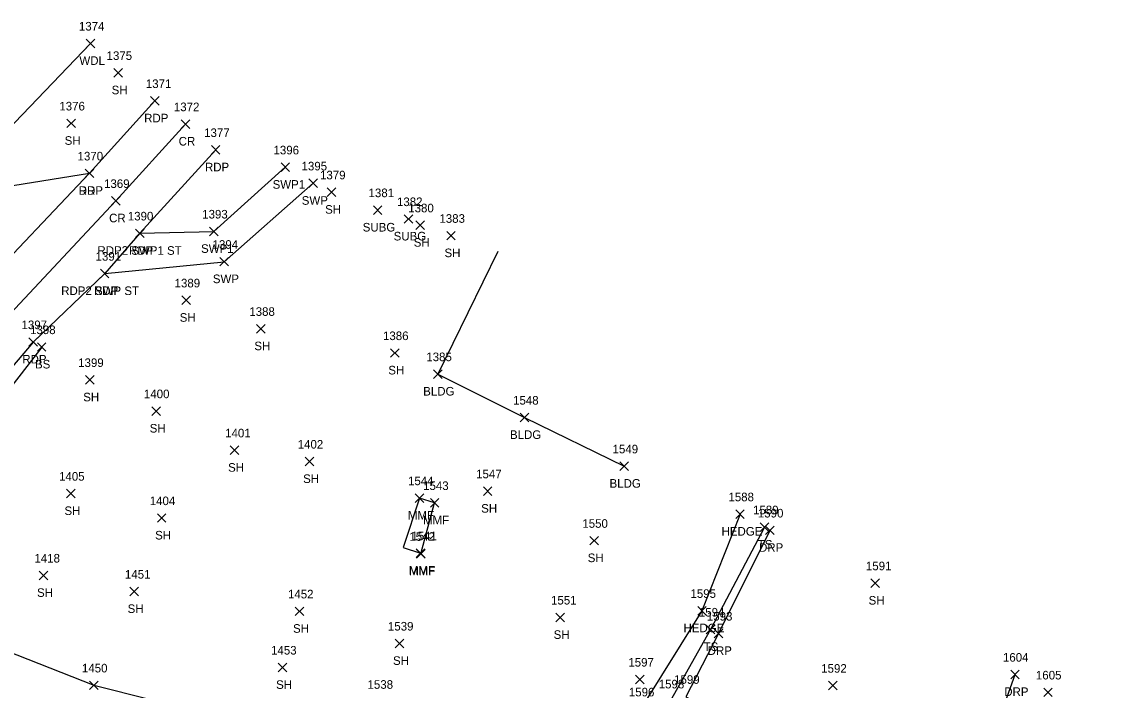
# Model space of a CAD drawing. Extents: x 1586965 to 1590952, y 716317 to 720029.
# Drawn here: x 1587807.3 to 1588061.4, y 719869.6 to 720025.2 of the extents above; entities that cross this region are included whole.
import ezdxf

# ---------------------------------------------------------------- set-up
doc = ezdxf.new("R2010")
doc.units = 0
for name, color, linetype in [('L_A', 7, 'Continuous'), ('L_I', 7, 'Continuous'), ('L_TIC', 7, 'Continuous'), ('LAHR', 7, 'Continuous'), ('LAWA', 7, 'Continuous'), ('LBC', 7, 'Continuous'), ('LDEFAULT', 7, 'Continuous'), ('LELB', 7, 'Continuous'), ('P_A', 7, 'Continuous'), ('P_I', 7, 'Continuous'), ('P_TIC', 7, 'Continuous'), ('PET', 7, 'Continuous'), ('PRC', 7, 'Continuous'), ('R_A', 7, 'Continuous'), ('R_I', 7, 'Continuous'), ('R_TIC', 7, 'Continuous'), ('RDP', 7, 'Continuous'), ('RSW', 7, 'Continuous'), ('U_A', 7, 'Continuous'), ('U_I', 7, 'Continuous'), ('U_TIC', 7, 'Continuous')]:
    doc.layers.add(name, color=color, linetype=linetype)

msp = doc.modelspace()

# ---------------------------------------------------------------- linework, layer by layer
at = {"layer": 'L_TIC'}
for points in [[(1587822.3, 720019.21), (1587824.3, 720021.21)], [(1587824.3, 720019.21), (1587822.3, 720021.21)], [(1587828.74, 720012.36), (1587830.74, 720014.36)], [(1587830.74, 720012.36), (1587828.74, 720014.36)], [(1587817.79, 720000.6), (1587819.79, 720002.6)], [(1587819.79, 720000.6), (1587817.79, 720002.6)], [(1587878.49, 719984.56), (1587880.49, 719986.56)], [(1587880.49, 719984.56), (1587878.49, 719986.56)], [(1587899.13, 719976.88), (1587901.13, 719978.88)], [(1587901.13, 719976.88), (1587899.13, 719978.88)], [(1587906.31, 719974.44), (1587908.31, 719976.44)], [(1587908.31, 719974.44), (1587906.31, 719976.44)], [(1587844.6, 719959.4), (1587846.6, 719961.4)], [(1587846.6, 719959.4), (1587844.6, 719961.4)], [(1587862, 719952.77), (1587864, 719954.77)], [(1587864, 719952.77), (1587862, 719954.77)], [(1587810.93, 719948.52), (1587812.93, 719950.52)], [(1587812.93, 719948.52), (1587810.93, 719950.52)], [(1587893.21, 719947.13), (1587895.21, 719949.13)], [(1587895.21, 719947.13), (1587893.21, 719949.13)], [(1587903.24, 719942.22), (1587905.24, 719944.22)], [(1587905.24, 719942.22), (1587903.24, 719944.22)], [(1587822.13, 719940.87), (1587824.13, 719942.87)], [(1587824.13, 719940.87), (1587822.13, 719942.87)], [(1587837.61, 719933.6), (1587839.61, 719935.6)], [(1587839.61, 719933.6), (1587837.61, 719935.6)], [(1587923.46, 719932.11), (1587925.46, 719934.11)], [(1587925.46, 719932.11), (1587923.46, 719934.11)], [(1587855.88, 719924.48), (1587857.88, 719926.48)], [(1587857.88, 719924.48), (1587855.88, 719926.48)], [(1587873.36, 719921.86), (1587875.36, 719923.86)], [(1587875.36, 719921.86), (1587873.36, 719923.86)], [(1587946.66, 719920.76), (1587948.66, 719922.76)], [(1587948.66, 719920.76), (1587946.66, 719922.76)], [(1587817.75, 719914.4), (1587819.75, 719916.4)], [(1587819.75, 719914.4), (1587817.75, 719916.4)], [(1587898.98, 719913.35), (1587900.98, 719915.35)], [(1587900.98, 719913.35), (1587898.98, 719915.35)], [(1587914.85, 719914.95), (1587916.85, 719916.95)], [(1587916.85, 719914.95), (1587914.85, 719916.95)], [(1587902.5, 719912.22), (1587904.5, 719914.22)], [(1587904.5, 719912.22), (1587902.5, 719914.22)], [(1587838.88, 719908.7), (1587840.88, 719910.7)], [(1587840.88, 719908.7), (1587838.88, 719910.7)], [(1587973.65, 719909.6), (1587975.65, 719911.6)], [(1587975.65, 719909.6), (1587973.65, 719911.6)], [(1587979.38, 719906.57), (1587981.38, 719908.57)], [(1587981.38, 719906.57), (1587979.38, 719908.57)], [(1587939.69, 719903.43), (1587941.69, 719905.43)], [(1587941.69, 719903.43), (1587939.69, 719905.43)], [(1587899.2, 719900.54), (1587901.2, 719902.54)], [(1587901.2, 719900.54), (1587899.2, 719902.54)], [(1587899.29, 719900.39), (1587901.29, 719902.39)], [(1587901.29, 719900.39), (1587899.29, 719902.39)], [(1587811.36, 719895.34), (1587813.36, 719897.34)], [(1587813.36, 719895.34), (1587811.36, 719897.34)], [(1588005.12, 719893.54), (1588007.12, 719895.54)], [(1588007.12, 719893.54), (1588005.12, 719895.54)], [(1587832.46, 719891.59), (1587834.46, 719893.59)], [(1587834.46, 719891.59), (1587832.46, 719893.59)], [(1587871.01, 719886.98), (1587873.01, 719888.98)], [(1587873.01, 719886.98), (1587871.01, 719888.98)], [(1587931.73, 719885.56), (1587933.73, 719887.56)], [(1587933.73, 719885.56), (1587931.73, 719887.56)], [(1587964.79, 719887.11), (1587966.79, 719889.11)], [(1587966.79, 719887.11), (1587964.79, 719889.11)], [(1587966.76, 719882.76), (1587968.76, 719884.76)], [(1587968.76, 719882.76), (1587966.76, 719884.76)], [(1587894.31, 719879.5), (1587896.31, 719881.5)], [(1587896.31, 719879.5), (1587894.31, 719881.5)], [(1587867.07, 719873.91), (1587869.07, 719875.91)], [(1587869.07, 719873.91), (1587867.07, 719875.91)], [(1587823.09, 719869.75), (1587825.09, 719871.75)], [(1587825.09, 719869.75), (1587823.09, 719871.75)], [(1587995.27, 719869.68), (1587997.27, 719871.68)], [(1587997.27, 719869.68), (1587995.27, 719871.68)], [(1588045.42, 719868.11), (1588047.42, 719870.11)], [(1588047.42, 719868.11), (1588045.42, 719870.11)]]:
    msp.add_lwpolyline(points, dxfattribs=at)
at = {"layer": 'LAHR'}
msp.add_lwpolyline([(1587974.65, 719910.6), (1587965.79, 719888.11), (1587951.5, 719865.17)], dxfattribs=at)
at = {"layer": 'LAWA'}
msp.add_lwpolyline([(1587759.78, 720023.49), (1587775.56, 720010.22), (1587793.08, 719998.06), (1587803.89, 719999.91), (1587823.3, 720020.21)], dxfattribs=at)
at = {"layer": 'LBC'}
msp.add_lwpolyline([(1587918.19, 719971.72), (1587904.24, 719943.22), (1587924.46, 719933.11), (1587947.66, 719921.76)], dxfattribs=at)
at = {"layer": 'LDEFAULT'}
for points in [[(1587896.16, 719902.84), (1587900.2, 719901.54), (1587900.29, 719901.39), (1587903.5, 719913.22), (1587899.98, 719914.35)], [(1587899.98, 719914.35), (1587896.16, 719902.84)]]:
    msp.add_lwpolyline(points, dxfattribs=at)
at = {"layer": 'LELB'}
for points in [[(1587811.93, 719949.52), (1587792.29, 719924.28), (1587790.61, 719906.24), (1587796.42, 719891.05), (1587800.94, 719879.86), (1587824.09, 719870.75), (1587863.89, 719860.75), (1587885.59, 719851.77), (1587915.12, 719838.63), (1587948, 719820.59), (1587984.49, 719804.22), (1588019.19, 719787.78), (1588025.35, 719786.55), (1588029.77, 719787.48), (1588038.8, 719793.55), (1588050.21, 719818.02), (1588057.55, 719835.32), (1588061.37, 719857.52)], [(1587811.93, 719949.52), (1587792.29, 719924.28), (1587790.61, 719906.24), (1587796.42, 719891.05), (1587800.94, 719879.86), (1587824.09, 719870.75), (1587863.89, 719860.75), (1587885.59, 719851.77), (1587915.12, 719838.63), (1587948, 719820.59), (1587984.49, 719804.22), (1588019.19, 719787.78), (1588025.35, 719786.55), (1588029.77, 719787.48), (1588038.8, 719793.55), (1588050.21, 719818.02), (1588057.55, 719835.32), (1588061.37, 719857.52)], [(1587980.38, 719907.57), (1587967.76, 719883.76), (1587958.41, 719867.03), (1587982.59, 719852.2), (1588028.36, 719838.74)], [(1587980.38, 719907.57), (1587967.76, 719883.76), (1587958.41, 719867.03), (1587982.59, 719852.2), (1588028.36, 719838.74)]]:
    msp.add_lwpolyline(points, dxfattribs=at)
at = {"layer": 'P_TIC'}
for points in [[(1587837.32, 720005.82), (1587839.32, 720007.82)], [(1587839.32, 720005.82), (1587837.32, 720007.82)], [(1587844.42, 720000.43), (1587846.42, 720002.43)], [(1587846.42, 720000.43), (1587844.42, 720002.43)], [(1587851.48, 719994.42), (1587853.48, 719996.42)], [(1587853.48, 719994.42), (1587851.48, 719996.42)], [(1587822.07, 719988.96), (1587824.07, 719990.96)], [(1587824.07, 719988.96), (1587822.07, 719990.96)], [(1587828.2, 719982.55), (1587830.2, 719984.55)], [(1587830.2, 719982.55), (1587828.2, 719984.55)], [(1587833.78, 719974.99), (1587835.78, 719976.99)], [(1587835.78, 719974.99), (1587833.78, 719976.99)], [(1587825.61, 719965.62), (1587827.61, 719967.62)], [(1587827.61, 719965.62), (1587825.61, 719967.62)], [(1587808.93, 719949.68), (1587810.93, 719951.68)], [(1587810.93, 719949.68), (1587808.93, 719951.68)]]:
    msp.add_lwpolyline(points, dxfattribs=at)
at = {"layer": 'PET'}
for points in [[(1587685.91, 719854.02), (1587701.42, 719870.84), (1587715.13, 719880.1), (1587736.18, 719901.89), (1587760.55, 719926.61), (1587776.13, 719942.57), (1587797.01, 719962.52), (1587823.07, 719989.96), (1587838.32, 720006.82)], [(1587852.48, 719995.42), (1587834.78, 719975.99), (1587826.61, 719966.62), (1587809.93, 719950.68), (1587788.43, 719925.43), (1587782.06, 719906.26), (1587783.24, 719885.08), (1587795.98, 719858.74)]]:
    msp.add_lwpolyline(points, dxfattribs=at)
at = {"layer": 'PRC'}
msp.add_lwpolyline([(1587717.2, 719859.97), (1587724.35, 719876.95), (1587738.37, 719893.54), (1587760.76, 719912.63), (1587787.69, 719938.18), (1587803.53, 719956.11), (1587829.2, 719983.55), (1587845.42, 720001.43)], dxfattribs=at)
msp.add_lwpolyline([(1587717.2, 719859.97), (1587724.35, 719876.95), (1587738.37, 719893.54), (1587760.76, 719912.63), (1587787.69, 719938.18), (1587803.53, 719956.11), (1587829.2, 719983.55), (1587845.42, 720001.43)], dxfattribs=at)
at = {"layer": 'R_TIC'}
for points in [[(1587867.7, 719990.37), (1587869.7, 719992.37)], [(1587869.7, 719990.37), (1587867.7, 719992.37)], [(1587822.07, 719988.96), (1587824.07, 719990.96)], [(1587824.07, 719988.96), (1587822.07, 719990.96)], [(1587874.17, 719986.64), (1587876.17, 719988.64)], [(1587876.17, 719986.64), (1587874.17, 719988.64)], [(1587833.78, 719974.99), (1587835.78, 719976.99)], [(1587835.78, 719974.99), (1587833.78, 719976.99)], [(1587851.03, 719975.44), (1587853.03, 719977.44)], [(1587853.03, 719975.44), (1587851.03, 719977.44)], [(1587853.44, 719968.39), (1587855.44, 719970.39)], [(1587855.44, 719968.39), (1587853.44, 719970.39)], [(1587825.61, 719965.62), (1587827.61, 719967.62)], [(1587827.61, 719965.62), (1587825.61, 719967.62)], [(1587980.59, 719905.83), (1587982.59, 719907.83)], [(1587982.59, 719905.83), (1587980.59, 719907.83)], [(1587968.62, 719881.82), (1587970.62, 719883.82)], [(1587970.62, 719881.82), (1587968.62, 719883.82)], [(1588037.73, 719872.26), (1588039.73, 719874.26)], [(1588039.73, 719872.26), (1588037.73, 719874.26)]]:
    msp.add_lwpolyline(points, dxfattribs=at)
at = {"layer": 'RDP'}
for points in [[(1587756.05, 720018.33), (1587771.73, 720004.93), (1587788.8, 719990.78), (1587803.23, 719986.78), (1587823.07, 719989.96)], [(1587981.59, 719906.83), (1587969.62, 719882.82), (1587961.99, 719868.1), (1587987.74, 719855.09), (1588029.05, 719846.17), (1588038.73, 719873.26)]]:
    msp.add_lwpolyline(points, dxfattribs=at)
at = {"layer": 'RSW'}
for points in [[(1587834.78, 719975.99), (1587852.03, 719976.44), (1587868.7, 719991.37)], [(1587826.61, 719966.62), (1587854.44, 719969.39), (1587875.17, 719987.64)]]:
    msp.add_lwpolyline(points, dxfattribs=at)
at = {"layer": 'U_TIC'}
for points in [[(1587889.21, 719980.41), (1587891.21, 719982.41)], [(1587891.21, 719980.41), (1587889.21, 719982.41)], [(1587896.42, 719978.33), (1587898.42, 719980.33)], [(1587898.42, 719978.33), (1587896.42, 719980.33)], [(1587950.32, 719871.11), (1587952.32, 719873.11)], [(1587952.32, 719871.11), (1587950.32, 719873.11)]]:
    msp.add_lwpolyline(points, dxfattribs=at)

# ---------------------------------------------------------------- texts
at = {"layer": 'L_A'}
for s, p in [('WDL', (1587820.72, 720015.21)), ('SH', (1587828.23, 720008.36)), ('SH', (1587817.28, 719996.6)), ('SH', (1587877.98, 719980.56)), ('SH', (1587898.62, 719972.88)), ('SH', (1587905.79, 719970.44)), ('SH', (1587844.09, 719955.4)), ('SH', (1587861.49, 719948.77)), ('BS', (1587810.37, 719944.52)), ('SH', (1587892.69, 719943.13)), ('SH', (1587821.61, 719936.87)), ('BLDG', (1587900.83, 719938.22)), ('SH', (1587837.1, 719929.6)), ('BLDG', (1587921.05, 719928.11)), ('SH', (1587855.37, 719920.48)), ('SH', (1587872.85, 719917.86)), ('BLDG', (1587944.25, 719916.76)), ('SH', (1587914.34, 719910.95)), ('SH', (1587817.24, 719910.4)), ('MMF', (1587897.26, 719909.35)), ('MMF', (1587900.78, 719908.22)), ('HEDGE', (1587970.35, 719905.6)), ('SH', (1587838.37, 719904.7)), ('TS', (1587978.79, 719902.57)), ('SH', (1587939.17, 719899.43)), ('MMF', (1587897.48, 719896.54)), ('MMF', (1587897.57, 719896.39)), ('SH', (1587810.85, 719891.34)), ('SH', (1588004.61, 719889.54)), ('SH', (1587831.95, 719887.59)), ('SH', (1587870.5, 719882.98)), ('HEDGE', (1587961.49, 719883.11)), ('SH', (1587931.22, 719881.56)), ('TS', (1587966.17, 719878.76)), ('SH', (1587893.8, 719875.5)), ('SH', (1587866.56, 719869.91))]:
    msp.add_text(s, height=2, dxfattribs=at).set_placement(p)
at = {"layer": 'L_I'}
for s, p in [('1374', (1587820.61, 720023.21)), ('1375', (1587827.05, 720016.36)), ('1376', (1587816.04, 720004.6)), ('1379', (1587876.79, 719988.56)), ('1380', (1587897.35, 719980.88)), ('1383', (1587904.61, 719978.44)), ('1389', (1587842.9, 719963.4)), ('1388', (1587860.31, 719956.77)), ('1398', (1587809.23, 719952.52)), ('1386', (1587891.46, 719951.13)), ('1385', (1587901.55, 719946.22)), ('1399', (1587820.43, 719944.87)), ('1400', (1587835.75, 719937.6)), ('1548', (1587921.77, 719936.11)), ('1401', (1587854.68, 719928.48)), ('1402', (1587871.59, 719925.86)), ('1549', (1587944.96, 719924.76)), ('1405', (1587815.98, 719918.4)), ('1547', (1587913.16, 719918.95)), ('1544', (1587897.29, 719917.35)), ('1543', (1587900.81, 719916.22)), ('1588', (1587971.95, 719913.6)), ('1404', (1587837.11, 719912.7)), ('1589', (1587977.68, 719910.57)), ('1550', (1587937.91, 719907.43)), ('1542', (1587897.6, 719904.39)), ('1541', (1587898.07, 719904.54)), ('1418', (1587810.24, 719899.34)), ('1451', (1587831.33, 719895.59)), ('1591', (1588003.99, 719897.54)), ('1452', (1587869.32, 719890.98)), ('1595', (1587963.1, 719891.11)), ('1551', (1587930.61, 719889.56)), ('1594', (1587965.07, 719886.76)), ('1539', (1587892.61, 719883.5)), ('1453', (1587865.38, 719877.91)), ('1450', (1587821.31, 719873.75)), ('1592', (1587993.57, 719873.68)), ('1538', (1587887.86, 719869.94)), ('1598', (1587955.71, 719870.03)), ('1605', (1588043.6, 719872.11)), ('1596', (1587948.75, 719868.17))]:
    msp.add_text(s, height=2, dxfattribs=at).set_placement(p)
at = {"layer": 'P_A'}
for s, p in [('RDP', (1587835.81, 720001.82)), ('CR', (1587843.85, 719996.43)), ('RDP', (1587849.97, 719990.42)), ('RDP', (1587820.56, 719984.96)), ('CR', (1587827.64, 719978.55)), ('RDP', (1587832.27, 719970.99)), ('RDP', (1587824.1, 719961.62)), ('RDP', (1587807.41, 719945.68))]:
    msp.add_text(s, height=2, dxfattribs=at).set_placement(p)
at = {"layer": 'P_I'}
for s, p in [('1371', (1587836.2, 720009.82)), ('1372', (1587842.73, 720004.43)), ('1377', (1587849.79, 719998.42)), ('1370', (1587820.29, 719992.96)), ('1369', (1587826.46, 719986.55)), ('1390', (1587832, 719978.99)), ('1391', (1587824.49, 719969.62)), ('1397', (1587807.23, 719953.68))]:
    msp.add_text(s, height=2, dxfattribs=at).set_placement(p)
at = {"layer": 'R_A'}
for s, p in [('DRP', (1587820.56, 719984.96)), ('SWP1', (1587865.74, 719986.37)), ('SWP', (1587872.53, 719982.64)), ('RDP2 SWP1 ST', (1587824.93, 719970.99)), ('SWP1', (1587849.07, 719971.44)), ('SWP', (1587851.81, 719964.39)), ('RDP2 SWP ST', (1587816.48, 719961.62)), ('DRP', (1587979.08, 719901.83)), ('DRP', (1587967.11, 719877.82)), ('DRP', (1588036.22, 719868.26))]:
    msp.add_text(s, height=2, dxfattribs=at).set_placement(p)
at = {"layer": 'R_I'}
for s, p in [('1370', (1587820.29, 719992.96)), ('1396', (1587865.95, 719994.37)), ('1395', (1587872.48, 719990.64)), ('1393', (1587849.33, 719979.44)), ('1390', (1587832, 719978.99)), ('1394', (1587851.75, 719972.39)), ('1391', (1587824.49, 719969.62)), ('1590', (1587978.81, 719909.83)), ('1593', (1587966.93, 719885.82)), ('1604', (1588035.92, 719876.26)), ('1599', (1587959.29, 719871.1))]:
    msp.add_text(s, height=2, dxfattribs=at).set_placement(p)
at = {"layer": 'U_A'}
for p in [(1587886.74, 719976.41), (1587893.94, 719974.33)]:
    msp.add_text('SUBG', height=2, dxfattribs=at).set_placement(p)
at = {"layer": 'U_I'}
for s, p in [('1381', (1587888.09, 719984.41)), ('1382', (1587894.72, 719982.33)), ('1597', (1587948.63, 719875.11))]:
    msp.add_text(s, height=2, dxfattribs=at).set_placement(p)

doc.saveas('drawing.dxf')
